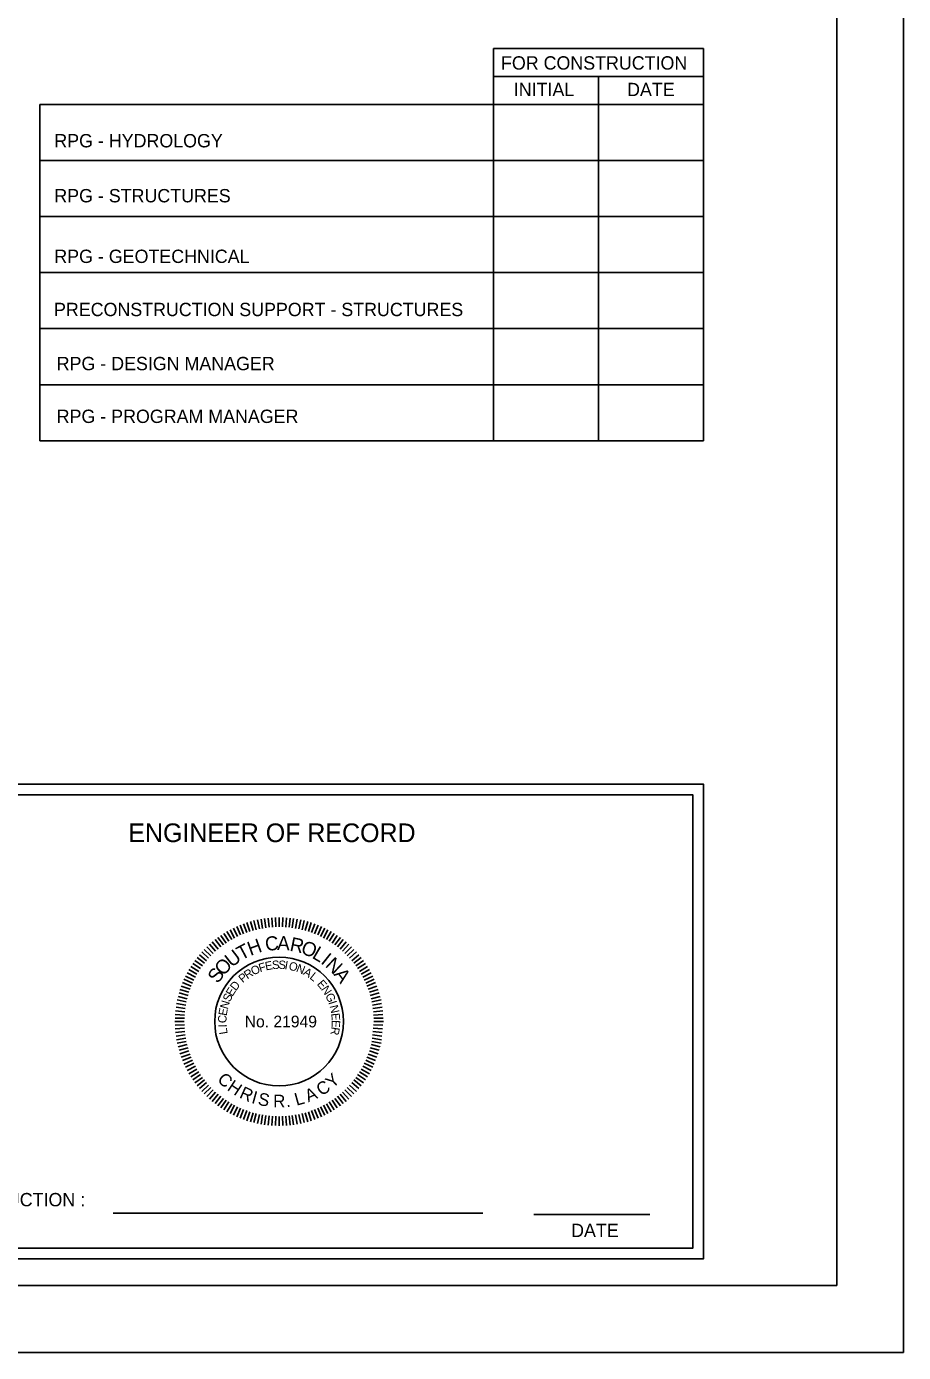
# Model space of a CAD drawing. Extents: x 140 to 1940, y 64 to 1307.
# Drawn here: x 1610.9 to 1939.6, y 63.9 to 561 of the extents above; entities that cross this region are included whole.
import ezdxf

# ---------------------------------------------------------------- set-up
doc = ezdxf.new("R2010")
doc.units = 0
for name, color, linetype in [('BR_BORDER LINES', 7, 'Continuous'), ('BR_DETAILS', 7, 'Continuous'), ('RD_SHT_IplotShp', 7, 'Continuous')]:
    doc.layers.add(name, color=color, linetype=linetype)

msp = doc.modelspace()

# ---------------------------------------------------------------- linework, layer by layer
at = {"layer": 'BR_BORDER LINES'}
for p, q in [((1914.58, 88.98), (1914.58, 1138.98)), ((239.58, 88.98), (1914.58, 88.98))]:
    msp.add_line(p, q, dxfattribs=at)
at = {"layer": 'BR_DETAILS'}
for p, q in [((1785.88, 552.71), (1864.58, 552.71)), ((1785.88, 405.71), (1785.88, 552.71)), ((1864.58, 552.71), (1864.58, 405.71)), ((1785.88, 542.21), (1864.58, 542.21)), ((1825.23, 542.21), (1825.23, 405.71)), ((1615.93, 531.71), (1864.58, 531.71)), ((1615.93, 405.71), (1615.93, 531.71)), ((1615.93, 510.71), (1864.58, 510.71)), ((1615.93, 489.71), (1864.58, 489.71)), ((1615.93, 468.71), (1864.58, 468.71)), ((1615.93, 447.71), (1864.58, 447.71)), ((1615.93, 426.71), (1864.58, 426.71)), ((1615.93, 405.71), (1864.58, 405.71)), ((1615.93, 405.71), (1858.38, 405.71)), ((1692.28, 220.85), (1690.97, 224.1)), ((1692.28, 220.85), (1690.97, 224.1)), ((1693.44, 221.3), (1692.24, 224.59)), ((1693.44, 221.3), (1692.24, 224.59)), ((1694.6, 221.74), (1693.51, 225.08)), ((1694.6, 221.74), (1693.51, 225.08)), ((1695.8, 222.06), (1694.83, 225.43)), ((1695.8, 222.06), (1694.83, 225.43)), ((1696.99, 222.38), (1696.15, 225.79)), ((1696.99, 222.38), (1696.15, 225.79)), ((1698.19, 222.71), (1697.46, 226.14)), ((1698.19, 222.71), (1697.46, 226.14)), ((1699.42, 222.9), (1698.81, 226.35)), ((1699.42, 222.9), (1698.81, 226.35)), ((1700.64, 223.09), (1700.15, 226.57)), ((1700.64, 223.09), (1700.15, 226.57)), ((1701.87, 223.29), (1701.5, 226.78)), ((1701.87, 223.29), (1701.5, 226.78)), ((1703.11, 223.35), (1702.86, 226.85)), ((1703.11, 223.35), (1702.86, 226.85)), ((1704.35, 223.42), (1704.22, 226.92)), ((1704.35, 223.42), (1704.22, 226.92)), ((1705.58, 223.48), (1705.58, 226.99)), ((1705.58, 223.48), (1705.58, 226.99)), ((1706.82, 223.42), (1706.95, 226.92)), ((1706.82, 223.42), (1706.95, 226.92)), ((1708.06, 223.35), (1708.31, 226.85)), ((1708.06, 223.35), (1708.31, 226.85)), ((1709.3, 223.29), (1709.67, 226.78)), ((1709.3, 223.29), (1709.67, 226.78)), ((1710.53, 223.09), (1711.01, 226.57)), ((1710.53, 223.09), (1711.01, 226.57)), ((1711.75, 222.9), (1712.36, 226.35)), ((1711.75, 222.9), (1712.36, 226.35)), ((1712.98, 222.71), (1713.71, 226.14)), ((1712.98, 222.71), (1713.71, 226.14)), ((1712.98, 222.71), (1713.71, 226.14)), ((1714.17, 222.38), (1715.02, 225.79)), ((1714.17, 222.38), (1715.02, 225.79)), ((1714.17, 222.38), (1715.02, 225.79)), ((1715.37, 222.06), (1716.34, 225.43)), ((1715.37, 222.06), (1716.34, 225.43)), ((1715.37, 222.06), (1716.34, 225.43)), ((1716.57, 221.74), (1717.66, 225.08)), ((1716.57, 221.74), (1717.66, 225.08)), ((1716.57, 221.74), (1717.66, 225.08)), ((1717.73, 221.3), (1718.93, 224.59)), ((1717.73, 221.3), (1718.93, 224.59)), ((1717.73, 221.3), (1718.93, 224.59)), ((1718.89, 220.85), (1720.2, 224.1)), ((1718.89, 220.85), (1720.2, 224.1)), ((1718.89, 220.85), (1720.2, 224.1)), ((1684.69, 216.69), (1682.62, 219.53)), ((1684.69, 216.69), (1682.62, 219.53)), ((1685.73, 217.37), (1683.77, 220.28)), ((1685.73, 217.37), (1683.77, 220.28)), ((1686.77, 218.04), (1684.91, 221.02)), ((1686.77, 218.04), (1684.91, 221.02)), ((1687.81, 218.72), (1686.05, 221.76)), ((1687.81, 218.72), (1686.05, 221.76)), ((1688.91, 219.28), (1687.27, 222.38)), ((1688.91, 219.28), (1687.27, 222.38)), ((1690.02, 219.84), (1688.48, 223)), ((1690.02, 219.84), (1688.48, 223)), ((1691.12, 220.41), (1689.7, 223.62)), ((1691.12, 220.41), (1689.7, 223.62)), ((1720.04, 220.41), (1721.47, 223.62)), ((1720.04, 220.41), (1721.47, 223.62)), ((1720.04, 220.41), (1721.47, 223.62)), ((1721.15, 219.84), (1722.69, 223)), ((1721.15, 219.84), (1722.69, 223)), ((1721.15, 219.84), (1722.69, 223)), ((1722.25, 219.28), (1723.9, 222.38)), ((1722.25, 219.28), (1723.9, 222.38)), ((1722.25, 219.28), (1723.9, 222.38)), ((1723.36, 218.72), (1725.12, 221.76)), ((1723.36, 218.72), (1725.12, 221.76)), ((1723.36, 218.72), (1725.12, 221.76)), ((1724.4, 218.04), (1726.26, 221.02)), ((1724.4, 218.04), (1726.26, 221.02)), ((1724.4, 218.04), (1726.26, 221.02)), ((1725.44, 217.37), (1727.4, 220.28)), ((1725.44, 217.37), (1727.4, 220.28)), ((1725.44, 217.37), (1727.4, 220.28)), ((1726.48, 216.69), (1728.54, 219.53)), ((1726.48, 216.69), (1728.54, 219.53)), ((1726.48, 216.69), (1728.54, 219.53)), ((1679.16, 211.72), (1676.56, 214.07)), ((1679.16, 211.72), (1676.56, 214.07)), ((1680.04, 212.6), (1677.52, 215.03)), ((1680.04, 212.6), (1677.52, 215.03)), ((1680.92, 213.47), (1678.48, 216)), ((1680.92, 213.47), (1678.48, 216)), ((1681.8, 214.35), (1679.45, 216.96)), ((1681.8, 214.35), (1679.45, 216.96)), ((1682.76, 215.13), (1680.51, 217.82)), ((1682.76, 215.13), (1680.51, 217.82)), ((1683.72, 215.91), (1681.56, 218.67)), ((1683.72, 215.91), (1681.56, 218.67)), ((1727.45, 215.91), (1729.6, 218.67)), ((1727.45, 215.91), (1729.6, 218.67)), ((1727.45, 215.91), (1729.6, 218.67)), ((1728.41, 215.13), (1730.66, 217.82)), ((1728.41, 215.13), (1730.66, 217.82)), ((1728.41, 215.13), (1730.66, 217.82)), ((1729.37, 214.35), (1731.72, 216.96)), ((1729.37, 214.35), (1731.72, 216.96)), ((1729.37, 214.35), (1731.72, 216.96)), ((1730.25, 213.47), (1732.69, 216)), ((1730.25, 213.47), (1732.69, 216)), ((1730.25, 213.47), (1732.69, 216)), ((1731.13, 212.6), (1733.65, 215.03)), ((1731.13, 212.6), (1733.65, 215.03)), ((1731.13, 212.6), (1733.65, 215.03)), ((1732, 211.72), (1734.61, 214.07)), ((1732, 211.72), (1734.61, 214.07)), ((1732, 211.72), (1734.61, 214.07)), ((1676.15, 207.79), (1673.24, 209.75)), ((1676.15, 207.79), (1673.24, 209.75)), ((1676.82, 208.83), (1673.98, 210.89)), ((1676.82, 208.83), (1673.98, 210.89)), ((1677.6, 209.79), (1674.84, 211.95)), ((1677.6, 209.79), (1674.84, 211.95)), ((1678.38, 210.75), (1675.7, 213.01)), ((1678.38, 210.75), (1675.7, 213.01)), ((1732.79, 210.75), (1735.47, 213.01)), ((1732.79, 210.75), (1735.47, 213.01)), ((1732.79, 210.75), (1735.47, 213.01)), ((1733.57, 209.79), (1736.33, 211.95)), ((1733.57, 209.79), (1736.33, 211.95)), ((1733.57, 209.79), (1736.33, 211.95)), ((1734.35, 208.83), (1737.19, 210.89)), ((1734.35, 208.83), (1737.19, 210.89)), ((1734.35, 208.83), (1737.19, 210.89)), ((1735.02, 207.79), (1737.93, 209.75)), ((1735.02, 207.79), (1737.93, 209.75)), ((1735.02, 207.79), (1737.93, 209.75)), ((1673.11, 202.39), (1669.9, 203.82)), ((1673.11, 202.39), (1669.9, 203.82)), ((1673.67, 203.5), (1670.52, 205.03)), ((1673.67, 203.5), (1670.52, 205.03)), ((1674.23, 204.6), (1671.14, 206.25)), ((1674.23, 204.6), (1671.14, 206.25)), ((1674.8, 205.71), (1671.76, 207.46)), ((1674.8, 205.71), (1671.76, 207.46)), ((1675.47, 206.75), (1672.5, 208.61)), ((1675.47, 206.75), (1672.5, 208.61)), ((1735.7, 206.75), (1738.67, 208.61)), ((1735.7, 206.75), (1738.67, 208.61)), ((1735.7, 206.75), (1738.67, 208.61)), ((1736.37, 205.71), (1739.41, 207.46)), ((1736.37, 205.71), (1739.41, 207.46)), ((1736.37, 205.71), (1739.41, 207.46)), ((1736.94, 204.6), (1740.03, 206.25)), ((1736.94, 204.6), (1740.03, 206.25)), ((1736.94, 204.6), (1740.03, 206.25)), ((1737.5, 203.5), (1740.65, 205.03)), ((1737.5, 203.5), (1740.65, 205.03)), ((1737.5, 203.5), (1740.65, 205.03)), ((1738.06, 202.39), (1741.27, 203.82)), ((1738.06, 202.39), (1741.27, 203.82)), ((1738.06, 202.39), (1741.27, 203.82)), ((1671.77, 198.92), (1668.43, 200)), ((1671.77, 198.92), (1668.43, 200)), ((1672.22, 200.08), (1668.92, 201.27)), ((1672.22, 200.08), (1668.92, 201.27)), ((1672.66, 201.23), (1669.41, 202.55)), ((1672.66, 201.23), (1669.41, 202.55)), ((1738.51, 201.23), (1741.76, 202.55)), ((1738.51, 201.23), (1741.76, 202.55)), ((1738.51, 201.23), (1741.76, 202.55)), ((1738.95, 200.08), (1742.25, 201.27)), ((1738.95, 200.08), (1742.25, 201.27)), ((1738.95, 200.08), (1742.25, 201.27)), ((1739.4, 198.92), (1742.74, 200)), ((1739.4, 198.92), (1742.74, 200)), ((1739.4, 198.92), (1742.74, 200)), ((1670.62, 194.1), (1667.16, 194.71)), ((1670.62, 194.1), (1667.16, 194.71)), ((1670.81, 195.32), (1667.38, 196.05)), ((1670.81, 195.32), (1667.38, 196.05)), ((1671.13, 196.52), (1667.73, 197.37)), ((1671.13, 196.52), (1667.73, 197.37)), ((1671.45, 197.72), (1668.08, 198.68)), ((1671.45, 197.72), (1668.08, 198.68)), ((1739.72, 197.72), (1743.09, 198.68)), ((1739.72, 197.72), (1743.09, 198.68)), ((1739.72, 197.72), (1743.09, 198.68)), ((1740.04, 196.52), (1743.44, 197.37)), ((1740.04, 196.52), (1743.44, 197.37)), ((1740.04, 196.52), (1743.44, 197.37)), ((1740.36, 195.32), (1743.79, 196.05)), ((1740.36, 195.32), (1743.79, 196.05)), ((1740.36, 195.32), (1743.79, 196.05)), ((1740.55, 194.1), (1744.01, 194.71)), ((1740.55, 194.1), (1744.01, 194.71)), ((1740.55, 194.1), (1744.01, 194.71)), ((1670.1, 189.17), (1666.59, 189.29)), ((1670.1, 189.17), (1666.59, 189.29)), ((1670.16, 190.41), (1666.66, 190.65)), ((1670.16, 190.41), (1666.66, 190.65)), ((1670.23, 191.65), (1666.74, 192.01)), ((1670.23, 191.65), (1666.74, 192.01)), ((1670.42, 192.87), (1666.95, 193.36)), ((1670.42, 192.87), (1666.95, 193.36)), ((1740.75, 192.87), (1744.22, 193.36)), ((1740.75, 192.87), (1744.22, 193.36)), ((1740.75, 192.87), (1744.22, 193.36)), ((1740.94, 191.65), (1744.43, 192.01)), ((1740.94, 191.65), (1744.43, 192.01)), ((1740.94, 191.65), (1744.43, 192.01)), ((1741.01, 190.41), (1744.5, 190.65)), ((1741.01, 190.41), (1744.5, 190.65)), ((1741.01, 190.41), (1744.5, 190.65)), ((1741.07, 189.17), (1744.58, 189.29)), ((1741.07, 189.17), (1744.58, 189.29)), ((1741.07, 189.17), (1744.58, 189.29)), ((1670.03, 187.93), (1666.52, 187.93)), ((1670.03, 187.93), (1666.52, 187.93)), ((1670.1, 186.69), (1666.59, 186.57)), ((1670.1, 186.69), (1666.59, 186.57)), ((1670.16, 185.45), (1666.66, 185.21)), ((1670.16, 185.45), (1666.66, 185.21)), ((1670.23, 184.21), (1666.74, 183.85)), ((1670.23, 184.21), (1666.74, 183.85)), ((1740.75, 184.23), (1744.22, 183.87)), ((1740.75, 184.23), (1744.22, 183.87)), ((1740.88, 185.46), (1744.36, 185.22)), ((1740.88, 185.46), (1744.36, 185.22)), ((1741.01, 186.69), (1744.5, 186.57)), ((1741.01, 186.69), (1744.5, 186.57)), ((1741.14, 187.93), (1744.65, 187.93)), ((1741.14, 187.93), (1744.65, 187.93)), ((1741.14, 187.93), (1744.65, 187.93)), ((1670.42, 182.99), (1666.95, 182.5)), ((1670.42, 182.99), (1666.95, 182.5)), ((1670.62, 181.76), (1667.16, 181.16)), ((1670.62, 181.76), (1667.16, 181.16)), ((1670.81, 180.54), (1667.38, 179.81)), ((1670.81, 180.54), (1667.38, 179.81)), ((1671.13, 179.34), (1667.73, 178.49)), ((1671.13, 179.34), (1667.73, 178.49)), ((1740.04, 179.34), (1743.44, 178.49)), ((1740.04, 179.34), (1743.44, 178.49)), ((1740.36, 180.54), (1743.79, 179.81)), ((1740.36, 180.54), (1743.79, 179.81)), ((1740.49, 181.78), (1743.94, 181.17)), ((1740.49, 181.78), (1743.94, 181.17)), ((1740.62, 183.01), (1744.08, 182.52)), ((1740.62, 183.01), (1744.08, 182.52)), ((1671.45, 178.14), (1668.08, 177.18)), ((1671.45, 178.14), (1668.08, 177.18)), ((1671.77, 176.94), (1668.43, 175.86)), ((1672.22, 175.79), (1668.92, 174.59)), ((1672.22, 175.79), (1668.92, 174.59)), ((1672.66, 174.63), (1669.41, 173.32)), ((1672.66, 174.63), (1669.41, 173.32)), ((1738.51, 174.63), (1741.76, 173.32)), ((1738.51, 174.63), (1741.76, 173.32)), ((1738.95, 175.79), (1742.25, 174.59)), ((1738.95, 175.79), (1742.25, 174.59)), ((1739.4, 176.94), (1742.74, 175.86)), ((1739.4, 176.94), (1742.74, 175.86)), ((1739.72, 178.14), (1743.09, 177.18)), ((1739.72, 178.14), (1743.09, 177.18)), ((1673.11, 173.47), (1669.9, 172.04)), ((1673.11, 173.47), (1669.9, 172.04)), ((1673.67, 172.36), (1670.52, 170.83)), ((1673.67, 172.36), (1670.52, 170.83)), ((1674.23, 171.26), (1671.14, 169.61)), ((1674.23, 171.26), (1671.14, 169.61)), ((1674.8, 170.15), (1671.76, 168.4)), ((1674.8, 170.15), (1671.76, 168.4)), ((1675.47, 169.11), (1672.5, 167.26)), ((1675.47, 169.11), (1672.5, 167.26)), ((1735.7, 169.11), (1738.67, 167.26)), ((1735.7, 169.11), (1738.67, 167.26)), ((1736.37, 170.15), (1739.41, 168.4)), ((1736.37, 170.15), (1739.41, 168.4)), ((1736.94, 171.26), (1740.03, 169.61)), ((1736.94, 171.26), (1740.03, 169.61)), ((1737.5, 172.36), (1740.65, 170.83)), ((1737.5, 172.36), (1740.65, 170.83)), ((1738.06, 173.47), (1741.27, 172.04)), ((1738.06, 173.47), (1741.27, 172.04)), ((1676.15, 168.07), (1673.24, 166.11)), ((1676.15, 168.07), (1673.24, 166.11)), ((1676.82, 167.03), (1673.98, 164.97)), ((1676.82, 167.03), (1673.98, 164.97)), ((1677.6, 166.07), (1674.84, 163.91)), ((1677.6, 166.07), (1674.84, 163.91)), ((1678.38, 165.11), (1675.7, 162.85)), ((1678.38, 165.11), (1675.7, 162.85)), ((1679.16, 164.14), (1676.56, 161.79)), ((1679.16, 164.14), (1676.56, 161.79)), ((1732, 164.14), (1734.61, 161.79)), ((1732, 164.14), (1734.61, 161.79)), ((1732.79, 165.11), (1735.47, 162.85)), ((1732.79, 165.11), (1735.47, 162.85)), ((1733.57, 166.07), (1736.33, 163.91)), ((1733.57, 166.07), (1736.33, 163.91)), ((1734.35, 167.03), (1737.19, 164.97)), ((1734.35, 167.03), (1737.19, 164.97)), ((1735.02, 168.07), (1737.93, 166.11)), ((1735.02, 168.07), (1737.93, 166.11)), ((1680.04, 163.26), (1677.52, 160.83)), ((1680.04, 163.26), (1677.52, 160.83)), ((1680.92, 162.39), (1678.48, 159.87)), ((1680.92, 162.39), (1678.48, 159.87)), ((1681.8, 161.51), (1679.45, 158.9)), ((1681.8, 161.51), (1679.45, 158.9)), ((1682.76, 160.73), (1680.51, 158.04)), ((1682.76, 160.73), (1680.51, 158.04)), ((1683.72, 159.95), (1681.56, 157.19)), ((1683.72, 159.95), (1681.56, 157.19)), ((1684.69, 159.17), (1682.62, 156.33)), ((1684.69, 159.17), (1682.62, 156.33)), ((1726.48, 159.17), (1728.54, 156.33)), ((1726.48, 159.17), (1728.54, 156.33)), ((1727.45, 159.95), (1729.6, 157.19)), ((1727.45, 159.95), (1729.6, 157.19)), ((1728.41, 160.73), (1730.66, 158.04)), ((1728.41, 160.73), (1730.66, 158.04)), ((1729.37, 161.51), (1731.72, 158.9)), ((1730.25, 162.39), (1732.69, 159.87)), ((1730.25, 162.39), (1732.69, 159.87)), ((1731.13, 163.26), (1733.65, 160.83)), ((1731.13, 163.26), (1733.65, 160.83)), ((1685.73, 158.49), (1683.77, 155.59)), ((1685.73, 158.49), (1683.77, 155.59)), ((1686.77, 157.82), (1684.91, 154.84)), ((1686.77, 157.82), (1684.91, 154.84)), ((1687.81, 157.14), (1686.05, 154.1)), ((1687.81, 157.14), (1686.05, 154.1)), ((1688.91, 156.58), (1687.27, 153.48)), ((1688.91, 156.58), (1687.27, 153.48)), ((1690.02, 156.02), (1688.48, 152.86)), ((1690.02, 156.02), (1688.48, 152.86)), ((1691.12, 155.45), (1689.7, 152.25)), ((1691.12, 155.45), (1689.7, 152.25)), ((1692.28, 155.01), (1690.97, 151.76)), ((1692.28, 155.01), (1690.97, 151.76)), ((1693.44, 154.56), (1692.24, 151.27)), ((1693.44, 154.56), (1692.24, 151.27)), ((1694.6, 154.12), (1693.51, 150.78)), ((1694.6, 154.12), (1693.51, 150.78)), ((1716.57, 154.12), (1717.66, 150.78)), ((1716.57, 154.12), (1717.66, 150.78)), ((1717.73, 154.56), (1718.93, 151.27)), ((1717.73, 154.56), (1718.93, 151.27)), ((1718.89, 155.01), (1720.2, 151.76)), ((1718.89, 155.01), (1720.2, 151.76)), ((1720.04, 155.45), (1721.47, 152.25)), ((1720.04, 155.45), (1721.47, 152.25)), ((1721.15, 156.02), (1722.69, 152.86)), ((1721.15, 156.02), (1722.69, 152.86)), ((1722.25, 156.58), (1723.9, 153.48)), ((1722.25, 156.58), (1723.9, 153.48)), ((1723.36, 157.14), (1725.12, 154.1)), ((1723.36, 157.14), (1725.12, 154.1)), ((1724.4, 157.82), (1726.26, 154.84)), ((1724.4, 157.82), (1726.26, 154.84)), ((1725.44, 158.49), (1727.4, 155.59)), ((1725.44, 158.49), (1727.4, 155.59)), ((1695.8, 153.8), (1694.83, 150.43)), ((1695.8, 153.8), (1694.83, 150.43)), ((1696.99, 153.48), (1696.15, 150.07)), ((1696.99, 153.48), (1696.15, 150.07)), ((1698.19, 153.16), (1697.46, 149.72)), ((1698.19, 153.16), (1697.46, 149.72)), ((1699.42, 152.96), (1698.81, 149.51)), ((1699.42, 152.96), (1698.81, 149.51)), ((1700.64, 152.77), (1700.15, 149.3)), ((1700.64, 152.77), (1700.15, 149.3)), ((1701.87, 152.57), (1701.5, 149.08)), ((1701.87, 152.57), (1701.5, 149.08)), ((1703.11, 152.51), (1702.86, 149.01)), ((1703.11, 152.51), (1702.86, 149.01)), ((1704.35, 152.44), (1704.22, 148.94)), ((1704.35, 152.44), (1704.22, 148.94)), ((1705.58, 152.38), (1705.58, 148.87)), ((1705.58, 152.38), (1705.58, 148.87)), ((1706.82, 152.44), (1706.95, 148.94)), ((1706.82, 152.44), (1706.95, 148.94)), ((1708.06, 152.51), (1708.31, 149.01)), ((1708.06, 152.51), (1708.31, 149.01)), ((1709.3, 152.57), (1709.67, 149.08)), ((1709.3, 152.57), (1709.67, 149.08)), ((1710.53, 152.77), (1711.01, 149.3)), ((1710.53, 152.77), (1711.01, 149.3)), ((1711.75, 152.96), (1712.36, 149.51)), ((1711.75, 152.96), (1712.36, 149.51)), ((1712.98, 153.16), (1713.71, 149.72)), ((1712.98, 153.16), (1713.71, 149.72)), ((1714.17, 153.48), (1715.02, 150.07)), ((1714.17, 153.48), (1715.02, 150.07)), ((1715.37, 153.8), (1716.34, 150.43)), ((1715.37, 153.8), (1716.34, 150.43)), ((1643.34, 116.16), (1781.97, 116.16)), ((1801.08, 115.6), (1844.56, 115.6))]:
    msp.add_line(p, q, dxfattribs=at)
for points in [[(1546.58, 276.98), (1864.58, 276.98), (1864.58, 98.98), (1546.58, 98.98)], [(1550.58, 272.98), (1860.58, 272.98), (1860.58, 102.98), (1550.58, 102.98)]]:
    msp.add_lwpolyline(points, close=True, dxfattribs=at)
msp.add_circle((1705.58, 187.98), 24.14, dxfattribs=at)
at = {"layer": 'RD_SHT_IplotShp'}
msp.add_lwpolyline([(139.58, 1163.91), (1939.58, 1163.91), (1939.58, 63.91), (139.58, 63.91)], close=True, dxfattribs=at)

# ---------------------------------------------------------------- texts
at = {"layer": 'BR_DETAILS'}
for s, height, rotation, p in [('FOR CONSTRUCTION', 4.998, 360, (1788.75, 544.83)), ('INITIAL', 4.998, 360, (1793.55, 534.87)), ('DATE', 4.998, 360, (1836, 534.87)), ('H', 5.27, 19.9102, (1694.83, 212.55)), ('C', 5.27, 6.8832, (1700.65, 214.35)), ('A', 5.27, 357.9448, (1704.8, 214.79)), ('R', 5.27, 348.267, (1709.32, 214.54)), ('U', 5.27, 37.7726, (1687.81, 208.07)), ('T', 5.27, 28.0947, (1691.44, 210.77)), ('O', 5.27, 339.3286, (1713.41, 213.64)), ('L', 5.27, 329.6507, (1717.61, 211.96)), ('O', 5.27, 47.4504, (1684.68, 204.8)), ('O', 3.16, 25.285, (1695.88, 205.2)), ('F', 3.16, 17.0454, (1698.45, 206.41)), ('E', 3.16, 10.5018, (1700.6, 207.11)), ('S', 3.16, 3.4002, (1703, 207.58)), ('S', 3.16, 356.8566, (1705.25, 207.74)), ('I', 3.16, 350.313, (1707.51, 207.65)), ('O', 3.16, 346.0455, (1708.96, 207.46)), ('N', 3.16, 337.8059, (1711.72, 206.77)), ('I', 5.27, 321.4663, (1720.9, 210)), ('N', 5.27, 317.0007, (1722.57, 208.74)), ('S', 5.27, 54.9027, (1682.68, 201.94)), ('P', 3.16, 39.5047, (1691.95, 202.29)), ('R', 3.16, 32.9611, (1693.67, 203.75)), ('A', 3.16, 329.5663, (1714.35, 205.7)), ('L', 3.16, 321.3267, (1716.8, 204.26)), ('A', 5.27, 307.3229, (1725.82, 205.59)), ('E', 3.16, 58.2627, (1688.07, 197.14)), ('D', 3.16, 51.1611, (1689.33, 199.24)), ('E', 3.16, 310.8083, (1719.58, 201.94)), ('N', 3.16, 303.7068, (1721.2, 200.1)), ('N', 3.16, 73.0458, (1686.31, 192.37)), ('S', 3.16, 64.8063, (1687.14, 195.09)), ('G', 3.16, 295.4672, (1722.78, 197.73)), ('I', 3.16, 287.2276, (1724, 195.17)), ('N', 3.16, 282.96, (1724.49, 193.78)), ('C', 3.16, 87.8235, (1685.82, 187.31)), ('E', 3.16, 80.1474, (1685.91, 189.95)), ('E', 3.16, 274.7205, (1725.12, 191.01)), ('I', 3.16, 92.0911, (1685.93, 185.84)), ('L', 3.16, 99.1926, (1686.34, 183.42)), ('R', 3.16, 260.5173, (1725.27, 186.12)), ('E', 3.16, 267.6189, (1725.35, 188.57)), ('C', 4.73, 317.0914, (1682.1, 165.85)), ('H', 4.73, 326.011, (1685.82, 162.48)), ('C', 4.73, 33.2512, (1721.45, 159.89)), ('Y', 4.73, 42.1707, (1725.61, 162.68)), ('R', 4.73, 335.6684, (1690.38, 159.53)), ('I', 4.73, 344.5879, (1694.97, 157.51)), ('S', 4.73, 349.0441, (1697.37, 156.78)), ('R', 4.73, 359.8228, (1703.35, 155.79)), ('L', 4.73, 15.4265, (1712.09, 156.38)), ('A', 4.73, 23.5938, (1716.51, 157.62)), ('.', 4.73, 8.7423, (1708.36, 155.84))]:
    msp.add_text(s, height=height, rotation=rotation, dxfattribs=at).set_placement(p)
for s, height, p in [('RPG - HYDROLOGY ', 4.998, (1621.34, 515.67)), ('RPG - STRUCTURES', 4.998, (1621.34, 495.06)), ('RPG - GEOTECHNICAL', 4.998, (1621.34, 472.33)), ('PRECONSTRUCTION SUPPORT - STRUCTURES', 4.998, (1621.22, 452.4)), ('RPG - DESIGN MANAGER', 4.998, (1622.23, 432.13)), ('RPG - PROGRAM MANAGER', 4.998, (1622.23, 412.35)), ('ENGINEER OF RECORD', 7, (1649.08, 255.23)), ('No. 21949', 4.389, (1692.69, 185.78)), ('FOR CONSTRUCTION :', 5.0001, (1559.35, 118.7)), ('DATE', 5, (1815.02, 107.18))]:
    msp.add_text(s, height=height, dxfattribs=at).set_placement(p)

doc.saveas('drawing.dxf')
